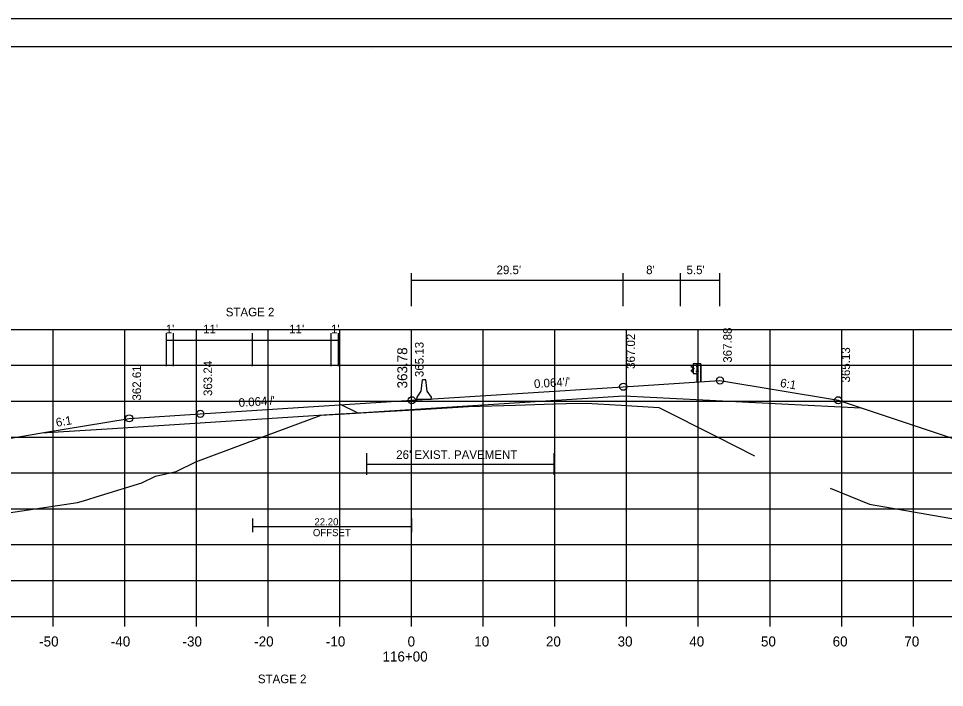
# Model space of a CAD drawing. Extents: x 1374859 to 1376773, y 382242 to 389804.
# Drawn here: x 1376555.6 to 1376684.8, y 383428.5 to 383521.8 of the extents above; entities that cross this region are included whole.
import ezdxf

# ---------------------------------------------------------------- set-up
doc = ezdxf.new("R2010")
doc.units = 0
for name, color, linetype in [('R_Axis', 7, 'Continuous'), ('R_Axis Annot', 7, 'Continuous'), ('R_Border', 7, 'Continuous'), ('R_Border Notes', 7, 'Continuous'), ('R_Draft', 7, 'Continuous'), ('R_Drive', 7, 'Continuous'), ('R_Exist Surface', 7, 'Continuous'), ('R_Fin Surface', 7, 'Continuous'), ('R_Grid', 7, 'Continuous'), ('R_MOT', 7, 'Continuous'), ('R_No Plot', 7, 'Continuous'), ('R_Proposed Road', 7, 'Continuous'), ('R_Xsect Elev', 7, 'Continuous'), ('R_Xsect Slope', 7, 'Continuous')]:
    doc.layers.add(name, color=color, linetype=linetype)

msp = doc.modelspace()

# ---------------------------------------------------------------- linework, layer by layer
at = {"layer": 'R_Axis'}
for p, q in [((1376470.45, 383438.41), (1376750.45, 383438.41)), ((1376560.45, 383437.01), (1376560.45, 383438.41)), ((1376570.45, 383437.01), (1376570.45, 383438.41)), ((1376580.45, 383437.01), (1376580.45, 383438.41)), ((1376590.45, 383437.01), (1376590.45, 383438.41)), ((1376600.45, 383437.01), (1376600.45, 383438.41)), ((1376610.45, 383437.01), (1376610.45, 383438.41)), ((1376620.45, 383437.01), (1376620.45, 383438.41)), ((1376630.45, 383437.01), (1376630.45, 383438.41)), ((1376640.45, 383437.01), (1376640.45, 383438.41)), ((1376650.45, 383437.01), (1376650.45, 383438.41)), ((1376660.45, 383437.01), (1376660.45, 383438.41)), ((1376670.45, 383437.01), (1376670.45, 383438.41)), ((1376680.45, 383437.01), (1376680.45, 383438.41))]:
    msp.add_line(p, q, dxfattribs=at)
at = {"layer": 'R_Border'}
for p, q in [((1376452.45, 383517.87), (1376768.63, 383517.87)), ((1376604.97, 383517.61), (1376604.97, 383517.61)), ((1376604.97, 383517.61), (1376604.97, 383517.61))]:
    msp.add_line(p, q, dxfattribs=at)
at = {"layer": 'R_Border Notes'}
for points in [[(1376604.16, 383461.15), (1376604.16, 383458.15)], [(1376630.28, 383461.15), (1376630.28, 383458.15)], [(1376604.16, 383459.65), (1376630.28, 383459.65)]]:
    msp.add_lwpolyline(points, dxfattribs=at)
at = {"layer": 'R_Drive'}
msp.add_line((1376602.89, 383466.77), (1376600.53, 383467.95), dxfattribs=at)
at = {"layer": 'R_Exist Surface'}
for points in [[(1376554.2, 383452.85), (1376563.83, 383454.29), (1376564.65, 383454.5), (1376567.06, 383455.26), (1376572.82, 383457.01), (1376574.71, 383457.95), (1376577.58, 383458.6), (1376580.33, 383459.95), (1376587.18, 383462.51), (1376597.84, 383466.45), (1376601.08, 383466.65), (1376604.16, 383466.85), (1376611.69, 383467.26), (1376618.4, 383467.66), (1376624.95, 383467.86), (1376630.28, 383468.02), (1376632.01, 383468.07), (1376634.82, 383468.14), (1376639.67, 383467.86), (1376644.93, 383467.55), (1376652.98, 383463.51), (1376658.27, 383460.79)], [(1376668.85, 383456.3), (1376674.33, 383454.05), (1376698.32, 383449.88), (1376699.46, 383449.76), (1376699.85, 383449.67), (1376707.88, 383448.53), (1376708.98, 383448.35), (1376711.42, 383448.61), (1376727.62, 383449.38), (1376737.96, 383449.29), (1376750.45, 383449.46)]]:
    msp.add_lwpolyline(points, dxfattribs=at)
at = {"layer": 'R_Fin Surface'}
for points in [[(1376485.18, 383452.49), (1376502.81, 383446.62), (1376550.97, 383462.67), (1376558.85, 383463.98), (1376571.04, 383466.02), (1376580.97, 383466.65), (1376610.47, 383468.54), (1376639.97, 383470.43), (1376653.47, 383471.29), (1376669.72, 383468.58), (1376669.97, 383468.54), (1376729.76, 383448.61), (1376731.96, 383449.34)], [(1376558.86, 383463.98), (1376568.74, 383464.62), (1376598.22, 383466.51), (1376603.72, 383466.85), (1376640.05, 383469.18), (1376673.13, 383467.49)]]:
    msp.add_lwpolyline(points, dxfattribs=at)
at = {"layer": 'R_Grid'}
for p, q in [((1376470.45, 383478.41), (1376750.45, 383478.41)), ((1376470.45, 383478.41), (1376750.45, 383478.41)), ((1376560.45, 383438.41), (1376560.45, 383478.41)), ((1376560.45, 383438.41), (1376560.45, 383478.41)), ((1376570.45, 383438.41), (1376570.45, 383478.41)), ((1376570.45, 383438.41), (1376570.45, 383478.41)), ((1376580.45, 383438.41), (1376580.45, 383478.41)), ((1376580.45, 383438.41), (1376580.45, 383478.41)), ((1376590.45, 383438.41), (1376590.45, 383478.41)), ((1376590.45, 383438.41), (1376590.45, 383478.41)), ((1376600.45, 383438.41), (1376600.45, 383478.41)), ((1376600.45, 383438.41), (1376600.45, 383478.41)), ((1376610.45, 383438.41), (1376610.45, 383478.41)), ((1376610.45, 383438.41), (1376610.45, 383478.41)), ((1376620.45, 383438.41), (1376620.45, 383478.41)), ((1376620.45, 383438.41), (1376620.45, 383478.41)), ((1376630.45, 383438.41), (1376630.45, 383478.41)), ((1376630.45, 383438.41), (1376630.45, 383478.41)), ((1376640.45, 383438.41), (1376640.45, 383478.41)), ((1376640.45, 383438.41), (1376640.45, 383478.41)), ((1376650.45, 383438.41), (1376650.45, 383478.41)), ((1376650.45, 383438.41), (1376650.45, 383478.41)), ((1376660.45, 383438.41), (1376660.45, 383478.41)), ((1376660.45, 383438.41), (1376660.45, 383478.41)), ((1376670.45, 383438.41), (1376670.45, 383478.41)), ((1376670.45, 383438.41), (1376670.45, 383478.41)), ((1376680.45, 383438.41), (1376680.45, 383478.41)), ((1376680.45, 383438.41), (1376680.45, 383478.41)), ((1376470.45, 383473.41), (1376750.45, 383473.41)), ((1376470.45, 383473.41), (1376750.45, 383473.41)), ((1376470.45, 383468.41), (1376750.45, 383468.41)), ((1376470.45, 383468.41), (1376750.45, 383468.41)), ((1376470.45, 383463.41), (1376750.45, 383463.41)), ((1376470.45, 383463.41), (1376750.45, 383463.41)), ((1376470.45, 383458.41), (1376750.45, 383458.41)), ((1376470.45, 383458.41), (1376750.45, 383458.41)), ((1376470.45, 383453.41), (1376750.45, 383453.41)), ((1376470.45, 383453.41), (1376750.45, 383453.41)), ((1376470.45, 383448.41), (1376750.45, 383448.41)), ((1376470.45, 383448.41), (1376750.45, 383448.41)), ((1376470.45, 383443.41), (1376750.45, 383443.41)), ((1376470.45, 383443.41), (1376750.45, 383443.41)), ((1376470.45, 383438.41), (1376750.45, 383438.41)), ((1376470.45, 383438.41), (1376750.45, 383438.41))]:
    msp.add_line(p, q, dxfattribs=at)
at = {"layer": 'R_MOT'}
for p, q in [((1376610.45, 383481.64), (1376610.45, 383486.27)), ((1376639.95, 383481.64), (1376639.95, 383486.27)), ((1376647.95, 383481.64), (1376647.95, 383486.27)), ((1376653.45, 383481.64), (1376653.45, 383486.27)), ((1376610.45, 383485.27), (1376653.45, 383485.27)), ((1376576.24, 383473.28), (1376576.24, 383477.91)), ((1376577.24, 383473.28), (1376577.24, 383477.91)), ((1376588.24, 383473.28), (1376588.24, 383477.91)), ((1376599.24, 383473.28), (1376599.24, 383477.91)), ((1376600.24, 383473.28), (1376600.24, 383477.91)), ((1376576.24, 383476.91), (1376600.24, 383476.91)), ((1376611.78, 383469.8), (1376611.95, 383471.38)), ((1376612.2, 383471.38), (1376611.95, 383471.38)), ((1376612.45, 383471.38), (1376612.2, 383471.38)), ((1376612.62, 383469.8), (1376612.45, 383471.38)), ((1376611.21, 383468.97), (1376611.78, 383469.8)), ((1376613.21, 383468.97), (1376612.62, 383469.8)), ((1376611.2, 383468.63), (1376611.21, 383468.97)), ((1376613.2, 383468.63), (1376611.2, 383468.63)), ((1376613.2, 383468.63), (1376613.21, 383468.97)), ((1376588.24, 383452.06), (1376588.24, 383450.13)), ((1376610.45, 383452.06), (1376610.45, 383450.13)), ((1376610.45, 383450.87), (1376588.24, 383450.87))]:
    msp.add_line(p, q, dxfattribs=at)
at = {"layer": 'R_No Plot'}
msp.add_line((1376440.05, 383521.76), (1376773.38, 383521.76), dxfattribs=at)
for points in [[(1376440.04, 383521.76), (1376773.38, 383521.76), (1376773.38, 383308.43), (1376440.04, 383308.43)], [(1376686.37, 383517.87), (1376686.37, 383507.99), (1376722.1, 383507.99), (1376722.1, 383505.07), (1376745.3, 383505.07), (1376745.3, 383480.74), (1376768.63, 383480.74), (1376768.63, 383312.41), (1376452.45, 383312.41), (1376452.45, 383517.87)]]:
    msp.add_lwpolyline(points, close=True, dxfattribs=at)
for centre in [(1376639.97, 383470.43), (1376653.47, 383471.29), (1376610.47, 383468.54), (1376669.97, 383468.54), (1376580.97, 383466.65), (1376571.04, 383466.02)]:
    msp.add_circle(centre, 0.5, dxfattribs=at)
at = {"layer": 'R_Proposed Road'}
for p, q in [((1376649.49, 383473.32), (1376649.62, 383473.42)), ((1376649.51, 383473.3), (1376649.64, 383473.41)), ((1376649.62, 383473.42), (1376649.74, 383473.48)), ((1376649.64, 383473.41), (1376649.73, 383473.46)), ((1376649.77, 383472.27), (1376649.77, 383473.63)), ((1376650.26, 383473.33), (1376650.21, 383473.33)), ((1376650.21, 383473.33), (1376650.21, 383473.21)), ((1376650.21, 383473.27), (1376650.27, 383473.27)), ((1376650.27, 383473.64), (1376650.27, 383473.64)), ((1376650.27, 383473.64), (1376650.34, 383473.64)), ((1376650.3, 383471.12), (1376650.3, 383473.64)), ((1376650.34, 383473.21), (1376650.34, 383473.34)), ((1376650.34, 383473.34), (1376650.39, 383473.34)), ((1376650.34, 383473.31), (1376650.39, 383473.31)), ((1376650.39, 383473.23), (1376650.39, 383473.32)), ((1376650.76, 383473.64), (1376650.76, 383471.12)), ((1376650.79, 383473.64), (1376650.79, 383471.12)), ((1376649.62, 383472.47), (1376649.49, 383472.58)), ((1376649.67, 383473.07), (1376649.5, 383473.18)), ((1376649.68, 383473.09), (1376649.51, 383473.2)), ((1376649.63, 383472.49), (1376649.51, 383472.6)), ((1376649.52, 383472.74), (1376649.67, 383472.84)), ((1376649.53, 383472.72), (1376649.69, 383472.82)), ((1376649.73, 383472.42), (1376649.62, 383472.47)), ((1376649.74, 383472.43), (1376649.63, 383472.49)), ((1376649.71, 383472.89), (1376649.7, 383473.02)), ((1376649.73, 383472.89), (1376649.73, 383473.02)), ((1376649.78, 383472.89), (1376649.78, 383473.02)), ((1376649.78, 383473.02), (1376649.83, 383473.02)), ((1376649.78, 383472.99), (1376649.83, 383472.99)), ((1376649.78, 383472.92), (1376649.82, 383472.92)), ((1376649.78, 383472.92), (1376649.83, 383472.92)), ((1376649.78, 383472.89), (1376649.83, 383472.89)), ((1376649.84, 383472.91), (1376649.84, 383473)), ((1376650.26, 383473.21), (1376650.21, 383473.21)), ((1376650.21, 383472.52), (1376650.21, 383472.65)), ((1376650.21, 383472.65), (1376650.26, 383472.65)), ((1376650.21, 383472.59), (1376650.27, 383472.59)), ((1376650.21, 383472.52), (1376650.26, 383472.52)), ((1376650.27, 383472.27), (1376650.3, 383472.27)), ((1376650.34, 383473.24), (1376650.38, 383473.24)), ((1376650.34, 383473.24), (1376650.39, 383473.24)), ((1376650.34, 383473.21), (1376650.39, 383473.21)), ((1376650.35, 383472.52), (1376650.35, 383472.65)), ((1376650.35, 383472.65), (1376650.4, 383472.65)), ((1376650.35, 383472.62), (1376650.4, 383472.62)), ((1376650.35, 383472.55), (1376650.39, 383472.55)), ((1376650.35, 383472.55), (1376650.4, 383472.55)), ((1376650.35, 383472.52), (1376650.4, 383472.52)), ((1376650.4, 383472.54), (1376650.4, 383472.63))]:
    msp.add_line(p, q, dxfattribs=at)
for points in [[(1376649.74, 383473.64), (1376649.74, 383472.27), (1376650.27, 383472.27), (1376650.27, 383473.64)], [(1376650.21, 383473.33), (1376650.21, 383473.21), (1376650.27, 383473.21), (1376650.27, 383473.33)], [(1376650.34, 383473.36), (1376650.34, 383473.19), (1376650.33, 383473.19), (1376650.33, 383473.36)], [(1376650.39, 383473.31), (1376650.39, 383473.24), (1376650.42, 383473.24), (1376650.42, 383473.31)], [(1376649.78, 383473.04), (1376649.78, 383472.87), (1376649.77, 383472.87), (1376649.77, 383473.04)], [(1376649.84, 383472.99), (1376649.84, 383472.92), (1376649.86, 383472.92), (1376649.86, 383472.99)], [(1376650.21, 383472.65), (1376650.21, 383472.52), (1376650.27, 383472.52), (1376650.27, 383472.65)], [(1376650.35, 383472.67), (1376650.35, 383472.5), (1376650.34, 383472.5), (1376650.34, 383472.67)], [(1376650.41, 383472.62), (1376650.41, 383472.55), (1376650.43, 383472.55), (1376650.43, 383472.62)]]:
    msp.add_lwpolyline(points, close=True, dxfattribs=at)
msp.add_lwpolyline([(1376650.79, 383473.64), (1376650.34, 383473.64), (1376650.34, 383471.12)], dxfattribs=at)
for centre, radius, start, end in [((1376649.54, 383473.25), 0.0856, 122.0217, 240.7501), ((1376649.54, 383473.25), 0.062, 122.0217, 240.7501), ((1376650.37, 383473.32), 0.022, 317.7756, 45.4255), ((1376650.3, 383473.27), 0.0922, 339.7423, 20.2577), ((1376649.58, 383472.65), 0.109, 120.88, 214.7816), ((1376649.58, 383472.65), 0.0854, 120.88, 214.7816), ((1376649.64, 383473.02), 0.0622, 4.9556, 61.894), ((1376649.71, 383472.95), 0.0453, 93.9303, 257.0446), ((1376649.64, 383473.02), 0.0865, 4.9556, 61.894), ((1376649.66, 383472.88), 0.0462, 293.1464, 8.2196), ((1376649.66, 383472.88), 0.0703, 293.1464, 8.2196), ((1376649.81, 383473), 0.022, 317.7756, 45.4255), ((1376649.74, 383472.95), 0.0922, 339.7423, 20.2577), ((1376649.81, 383472.91), 0.025, 323.3766, 39.0666), ((1376650.37, 383473.23), 0.025, 323.3766, 39.0666), ((1376650.38, 383472.63), 0.022, 317.7756, 45.4255), ((1376650.31, 383472.59), 0.0922, 339.7423, 20.2577), ((1376650.38, 383472.54), 0.025, 323.3766, 39.0666)]:
    msp.add_arc(centre, radius, start, end, dxfattribs=at)

# ---------------------------------------------------------------- texts
at = {"layer": 'R_Axis Annot'}
for s, p in [('-50', (1376558.49, 383434.21)), ('-40', (1376568.49, 383434.21)), ('-30', (1376578.49, 383434.21)), ('-20', (1376588.49, 383434.21)), ('-10', (1376598.49, 383434.21)), ('0', (1376609.89, 383434.21)), ('10', (1376619.19, 383434.21)), ('20', (1376629.19, 383434.21)), ('30', (1376639.19, 383434.21)), ('40', (1376649.19, 383434.21)), ('50', (1376659.19, 383434.21)), ('60', (1376669.19, 383434.21)), ('70', (1376679.19, 383434.21)), ('116+00', (1376606.39, 383432.11))]:
    msp.add_text(s, height=1.4, dxfattribs=at).set_placement(p)
at = {"layer": 'R_Border Notes'}
msp.add_text("26' EXIST. PAVEMENT", height=1.2, rotation=0, dxfattribs=at).set_placement((1376608.3, 383460.36))
at = {"layer": 'R_Draft'}
for s, p in [("22.20'", (1376596.89, 383451.09)), ('OFFSET', (1376596.68, 383449.59))]:
    msp.add_text(s, height=1, dxfattribs=at).set_placement(p)
at = {"layer": 'R_MOT'}
for s, p in [("29.5'", (1376622.3, 383486.12)), ("8'", (1376643.17, 383486.12)), ("5.5'", (1376648.8, 383486.12)), ("1'", (1376576.15, 383477.87)), ("11'", (1376581.36, 383477.87)), ("11'", (1376593.37, 383477.87)), ("1'", (1376599.21, 383477.87))]:
    msp.add_text(s, height=1.2, dxfattribs=at).set_placement(p)
for p in [(1376584.52, 383480.24), (1376589, 383429.09)]:
    msp.add_text('STAGE 2', height=1.2, rotation=0, dxfattribs=at).set_placement(p)
at = {"layer": 'R_Xsect Elev'}
for s, height, p in [('367.88', 1.2, (1376655.12, 383473.77)), ('367.02', 1.2, (1376641.62, 383472.91)), ('365.13', 1.2, (1376612.12, 383471.77)), ('365.13', 1.2, (1376671.62, 383471.02)), ('363.78', 1.4, (1376609.85, 383470.19)), ('362.61', 1.2, (1376572.7, 383468.5)), ('363.24', 1.2, (1376582.62, 383469.13))]:
    msp.add_text(s, height=height, rotation=90, dxfattribs=at).set_placement(p)
at = {"layer": 'R_Xsect Slope'}
for s, rotation, p in [("0.064'/'", 3.6633, (1376627.56, 383470.23)), ('6:1', 350.5358, (1376661.8, 383470.41)), ("0.064'/'", 3.6633, (1376586.35, 383467.6)), ('6:1', 9.4642, (1376560.92, 383464.83))]:
    msp.add_text(s, height=1.2, rotation=rotation, dxfattribs=at).set_placement(p)

doc.saveas('drawing.dxf')
